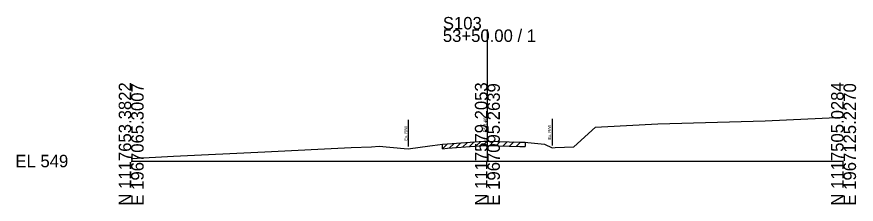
# Model space of a CAD drawing. Extents: x -26 to 163, y -10 to 24018.
# Drawn here: x -25.7 to 162.8, y 2990.3 to 3032.4 of the extents above; entities that cross this region are included whole.
import ezdxf

# ---------------------------------------------------------------- set-up
doc = ezdxf.new("R2010")
doc.units = 0
for name, color, linetype in [('RD_GPK_XS_Cell', 7, 'Continuous'), ('RD_XS_ExGround', 7, 'Continuous'), ('RD_XS_ExPaveRet', 7, 'Continuous'), ('RD_XS_ExRW', 7, 'Continuous'), ('RD_XS_TX_Elev_EX', 7, 'Continuous')]:
    doc.layers.add(name, color=color, linetype=linetype)

msp = doc.modelspace()

# ---------------------------------------------------------------- linework, layer by layer
at = {"layer": 'RD_GPK_XS_Cell'}
for p, q in [((80, 3000), (80, 3029.56)), ((0, 3000), (80, 3000)), ((80, 3000), (160, 3000))]:
    msp.add_line(p, q, dxfattribs=at)
at = {"layer": 'RD_XS_ExGround'}
msp.add_lwpolyline([(0, 3000.59), (9.49, 3001.08), (30.05, 3002.06), (49.38, 3003.01), (53.94, 3003.21), (55.66, 3003.31), (61.32, 3002.82), (62.24, 3002.74), (67.07, 3003.43), (67.64, 3003.53), (69.94, 3003.77), (71.07, 3003.87), (79.24, 3004.48), (80, 3004.46), (87.31, 3004.27), (88.49, 3004.25), (89.08, 3004.19), (92.81, 3003.81), (94.52, 3002.99), (95.26, 3003.01), (99.43, 3003.2), (104.3, 3007.6), (105.66, 3007.67), (118.26, 3008.35), (142.39, 3009.01), (160, 3009.85)], dxfattribs=at)
at = {"layer": 'RD_XS_ExPaveRet'}
for p, q in [((69.94, 3002.77), (71.03, 3003.86)), ((69.94, 3002.77), (69.94, 3003.77)), ((71.07, 3002.87), (79.24, 3003.48)), ((71.44, 3002.89), (72.52, 3003.97)), ((72.94, 3003), (74.02, 3004.09)), ((74.44, 3003.12), (75.52, 3004.2)), ((75.94, 3003.23), (77.02, 3004.31)), ((77.44, 3003.34), (78.52, 3004.42)), ((78.94, 3003.45), (79.94, 3004.46)), ((79.24, 3003.48), (80, 3003.46)), ((80, 3003.46), (87.31, 3003.27)), ((80.44, 3003.45), (81.41, 3004.42)), ((81.94, 3003.41), (82.91, 3004.38)), ((83.44, 3003.37), (84.41, 3004.35)), ((84.94, 3003.33), (85.91, 3004.31)), ((86.44, 3003.3), (87.41, 3004.27)), ((88.49, 3004.25), (88.49, 3003.25)), ((69.94, 3002.77), (71.07, 3002.87)), ((87.31, 3003.27), (88.49, 3003.25))]:
    msp.add_line(p, q, dxfattribs=at)
at = {"layer": 'RD_XS_ExRW'}
for p, q in [((62.24, 3009.24), (62.24, 3003.24)), ((94.52, 3009.49), (94.52, 3003.49))]:
    msp.add_line(p, q, dxfattribs=at)

# ---------------------------------------------------------------- texts
at = {"layer": 'RD_GPK_XS_Cell'}
for s, p in [('S103', (70, 3029.56)), ('53+50.00 / 1', (70, 3026.76)), ('EL 549', (-26, 2998.6))]:
    msp.add_text(s, height=2.8, dxfattribs=at).set_placement(p)
for s, p in [('N 1117653.3822', (0, 2990)), ('E 1967065.3007', (2.8, 2990)), ('N 1117579.2053', (80, 2990)), ('E 1967095.2639', (82.8, 2990)), ('N 1117505.0284', (160, 2990)), ('E 1967125.2270', (162.8, 2990))]:
    msp.add_text(s, height=2.8, rotation=90, dxfattribs=at).set_placement(p)
at = {"layer": 'RD_XS_ExRW'}
for p in [(61.99, 3004.58), (94.27, 3004.84)]:
    msp.add_text('Ex. R/W ', height=0.65, rotation=90, dxfattribs=at).set_placement(p)
at = {"layer": 'RD_XS_TX_Elev_EX'}
msp.add_text('553.46', height=0.8, rotation=90, dxfattribs=at).set_placement((79.9, 3006.46))

doc.saveas('drawing.dxf')
